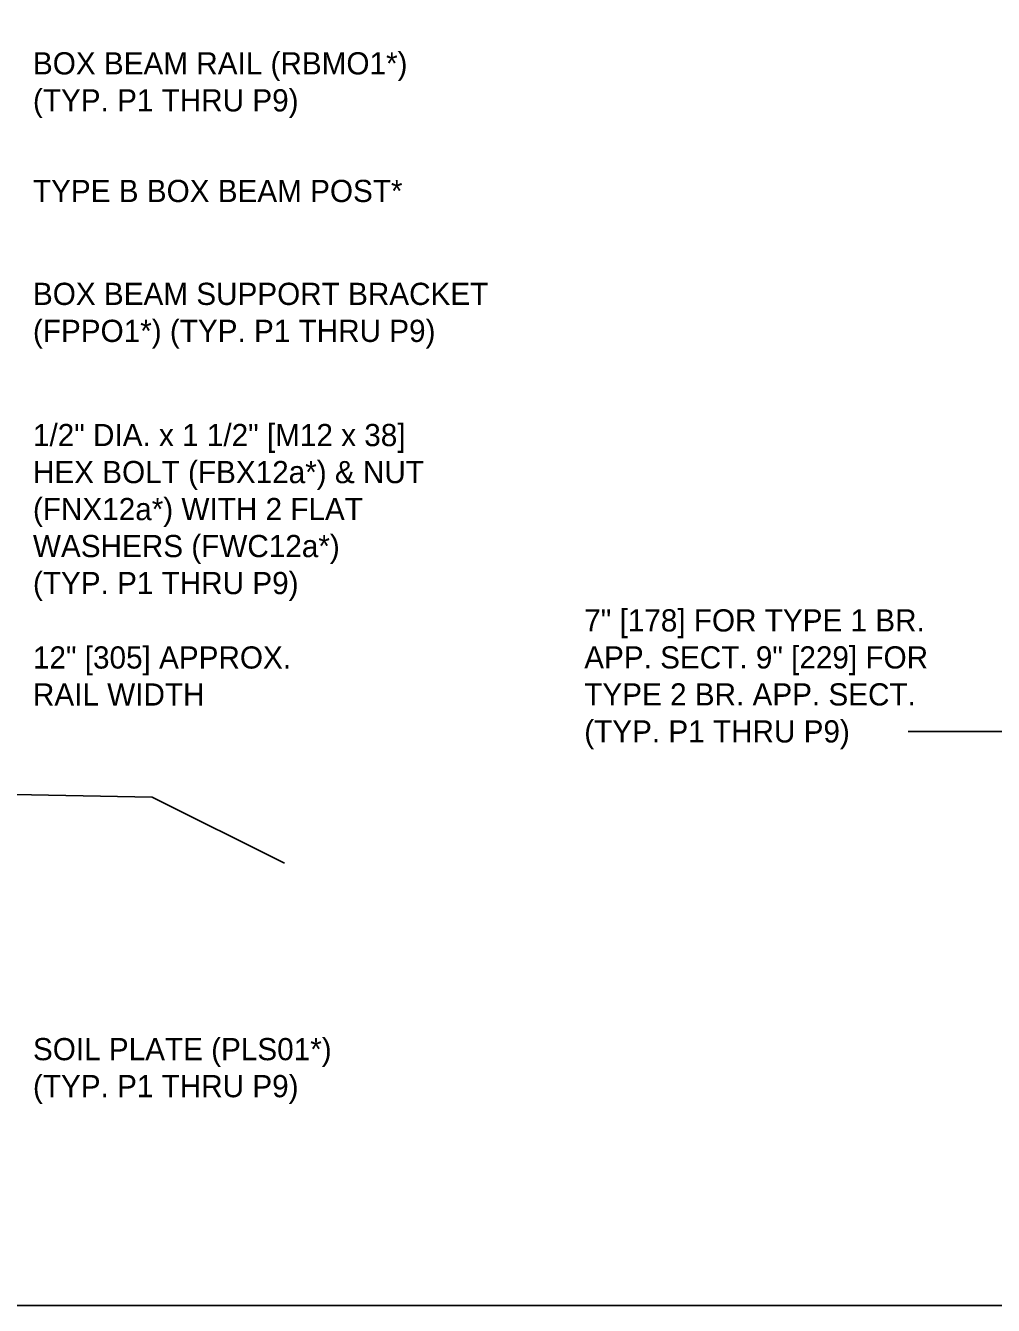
# Model space of a CAD drawing. Extents: x 49991.4 to 50021, y 49987.6 to 50011.4.
# Drawn here: x 50002.376 to 50004.991, y 49987.799 to 49991.258 of the extents above; entities that cross this region are included whole.
import ezdxf

# ---------------------------------------------------------------- set-up
doc = ezdxf.new("R2010")
doc.units = 0
for name, color, linetype in [('Level 1', 7, 'Continuous'), ('Level 2', 7, 'Continuous'), ('Level 3', 7, 'Continuous')]:
    doc.layers.add(name, color=color, linetype=linetype)

msp = doc.modelspace()

# ---------------------------------------------------------------- linework, layer by layer
at = {"layer": 'Level 1'}
for q in [(50002.0172, 49989.1865), (50003.0758, 49988.9936)]:
    msp.add_line((50002.7181, 49989.1725), q, dxfattribs=at)
msp.add_lwpolyline([(49999.3835, 49998.9992), (50016.7501, 49998.9992), (50016.7501, 49987.7988), (49999.3835, 49987.7988)], close=True, dxfattribs=at)
at = {"layer": 'Level 3'}
msp.add_line((50005.1074, 49989.3501), (50004.7612, 49989.3501), dxfattribs=at)

# ---------------------------------------------------------------- texts
at = {"layer": 'Level 2'}
for s, p in [('BOX BEAM RAIL (RBMO1*)', (50002.3959, 49991.1256)), ('(TYP. P1 THRU P9)', (50002.3959, 49991.0256)), ('TYPE B BOX BEAM POST*', (50002.3959, 49990.7807)), ('BOX BEAM SUPPORT BRACKET', (50002.3959, 49990.5026)), ('(FPPO1*) (TYP. P1 THRU P9)', (50002.3959, 49990.4026)), ('1/2" DIA. x 1 1/2" [M12 x 38] ', (50002.3959, 49990.121)), ('HEX BOLT (FBX12a*) & NUT ', (50002.3959, 49990.021)), ('(FNX12a*) WITH 2 FLAT ', (50002.3959, 49989.921)), ('WASHERS (FWC12a*) ', (50002.3959, 49989.821)), ('(TYP. P1 THRU P9)', (50002.3959, 49989.721)), ('7" [178] FOR TYPE 1 BR. ', (50003.8857, 49989.6201)), ('12" [305] APPROX.', (50002.3959, 49989.5199)), ('APP. SECT. 9" [229] FOR ', (50003.8857, 49989.5201)), ('RAIL WIDTH', (50002.3959, 49989.4199)), ('TYPE 2 BR. APP. SECT. ', (50003.8857, 49989.4201)), ('(TYP. P1 THRU P9)', (50003.8857, 49989.3201)), ('SOIL PLATE (PLS01*)', (50002.3959, 49988.4614)), ('(TYP. P1 THRU P9)', (50002.3959, 49988.3614))]:
    msp.add_text(s, height=0.06, dxfattribs=at).set_placement(p)

doc.saveas('drawing.dxf')
